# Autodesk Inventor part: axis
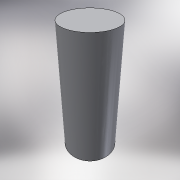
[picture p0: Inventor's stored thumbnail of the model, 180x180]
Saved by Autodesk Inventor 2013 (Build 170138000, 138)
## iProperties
Shininess: 64.0
Length Units: 11269
Angle Units: 11279
Time Units: 11290
Mass Units: 11283
Length Display Precision: 3
Angle Display Precision: 2
Compacted: True
Part Number: axis
Document SubType Name: Modeling
Created: 2005-02
Material: Aluminum 6061
Designer: =<Author>
Manufacturer: Standard
Standards Organization: Custom
Density: 2.71 g/cm^3
Description: shaft
Mass: 1.14935 g
Surface Area: 3.39292 cm^2
Volume: 0.424115 cm^3
Density: 0.0
Volumn: 0.0
Area: 0.0
PropertySet Name: Model Information
Control State: 0
Master: False
Checked Out: False
Checked Out Date: 2008-10-15
Last Check In Date: 2008-10-15
d0: 6.000 mm
d1: 15.000 mm
d2: 0.00 deg
Author: PVitaliy
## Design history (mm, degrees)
sketch "Эскиз1"
  geometry: C1 r 3 at (0, 0)
  constraints: 1 centre point, 1 other
  dimensions: "d0" = 6 dimension on C1.centre C1; "d0" = 6 diameter of C1
extrude "Выдавливание1" new body sketch "Эскиз1" distance "d1" = 15; taper "d2" = 0 deg
body "Solid1"
